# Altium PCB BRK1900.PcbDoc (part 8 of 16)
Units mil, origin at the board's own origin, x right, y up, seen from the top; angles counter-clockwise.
Board outline 8858.27 x 5905.51 mil, 10 copper layers (L1-TOP, L2-GND, L3-PWR, L4-GND, L5-PWR, L6-PWR, L7-GND, L8-SIG, L9-GND, L10-BOT), stack 48.824 mil thick; 456 components, 571 nets, 2296 pads, 2416 vias.
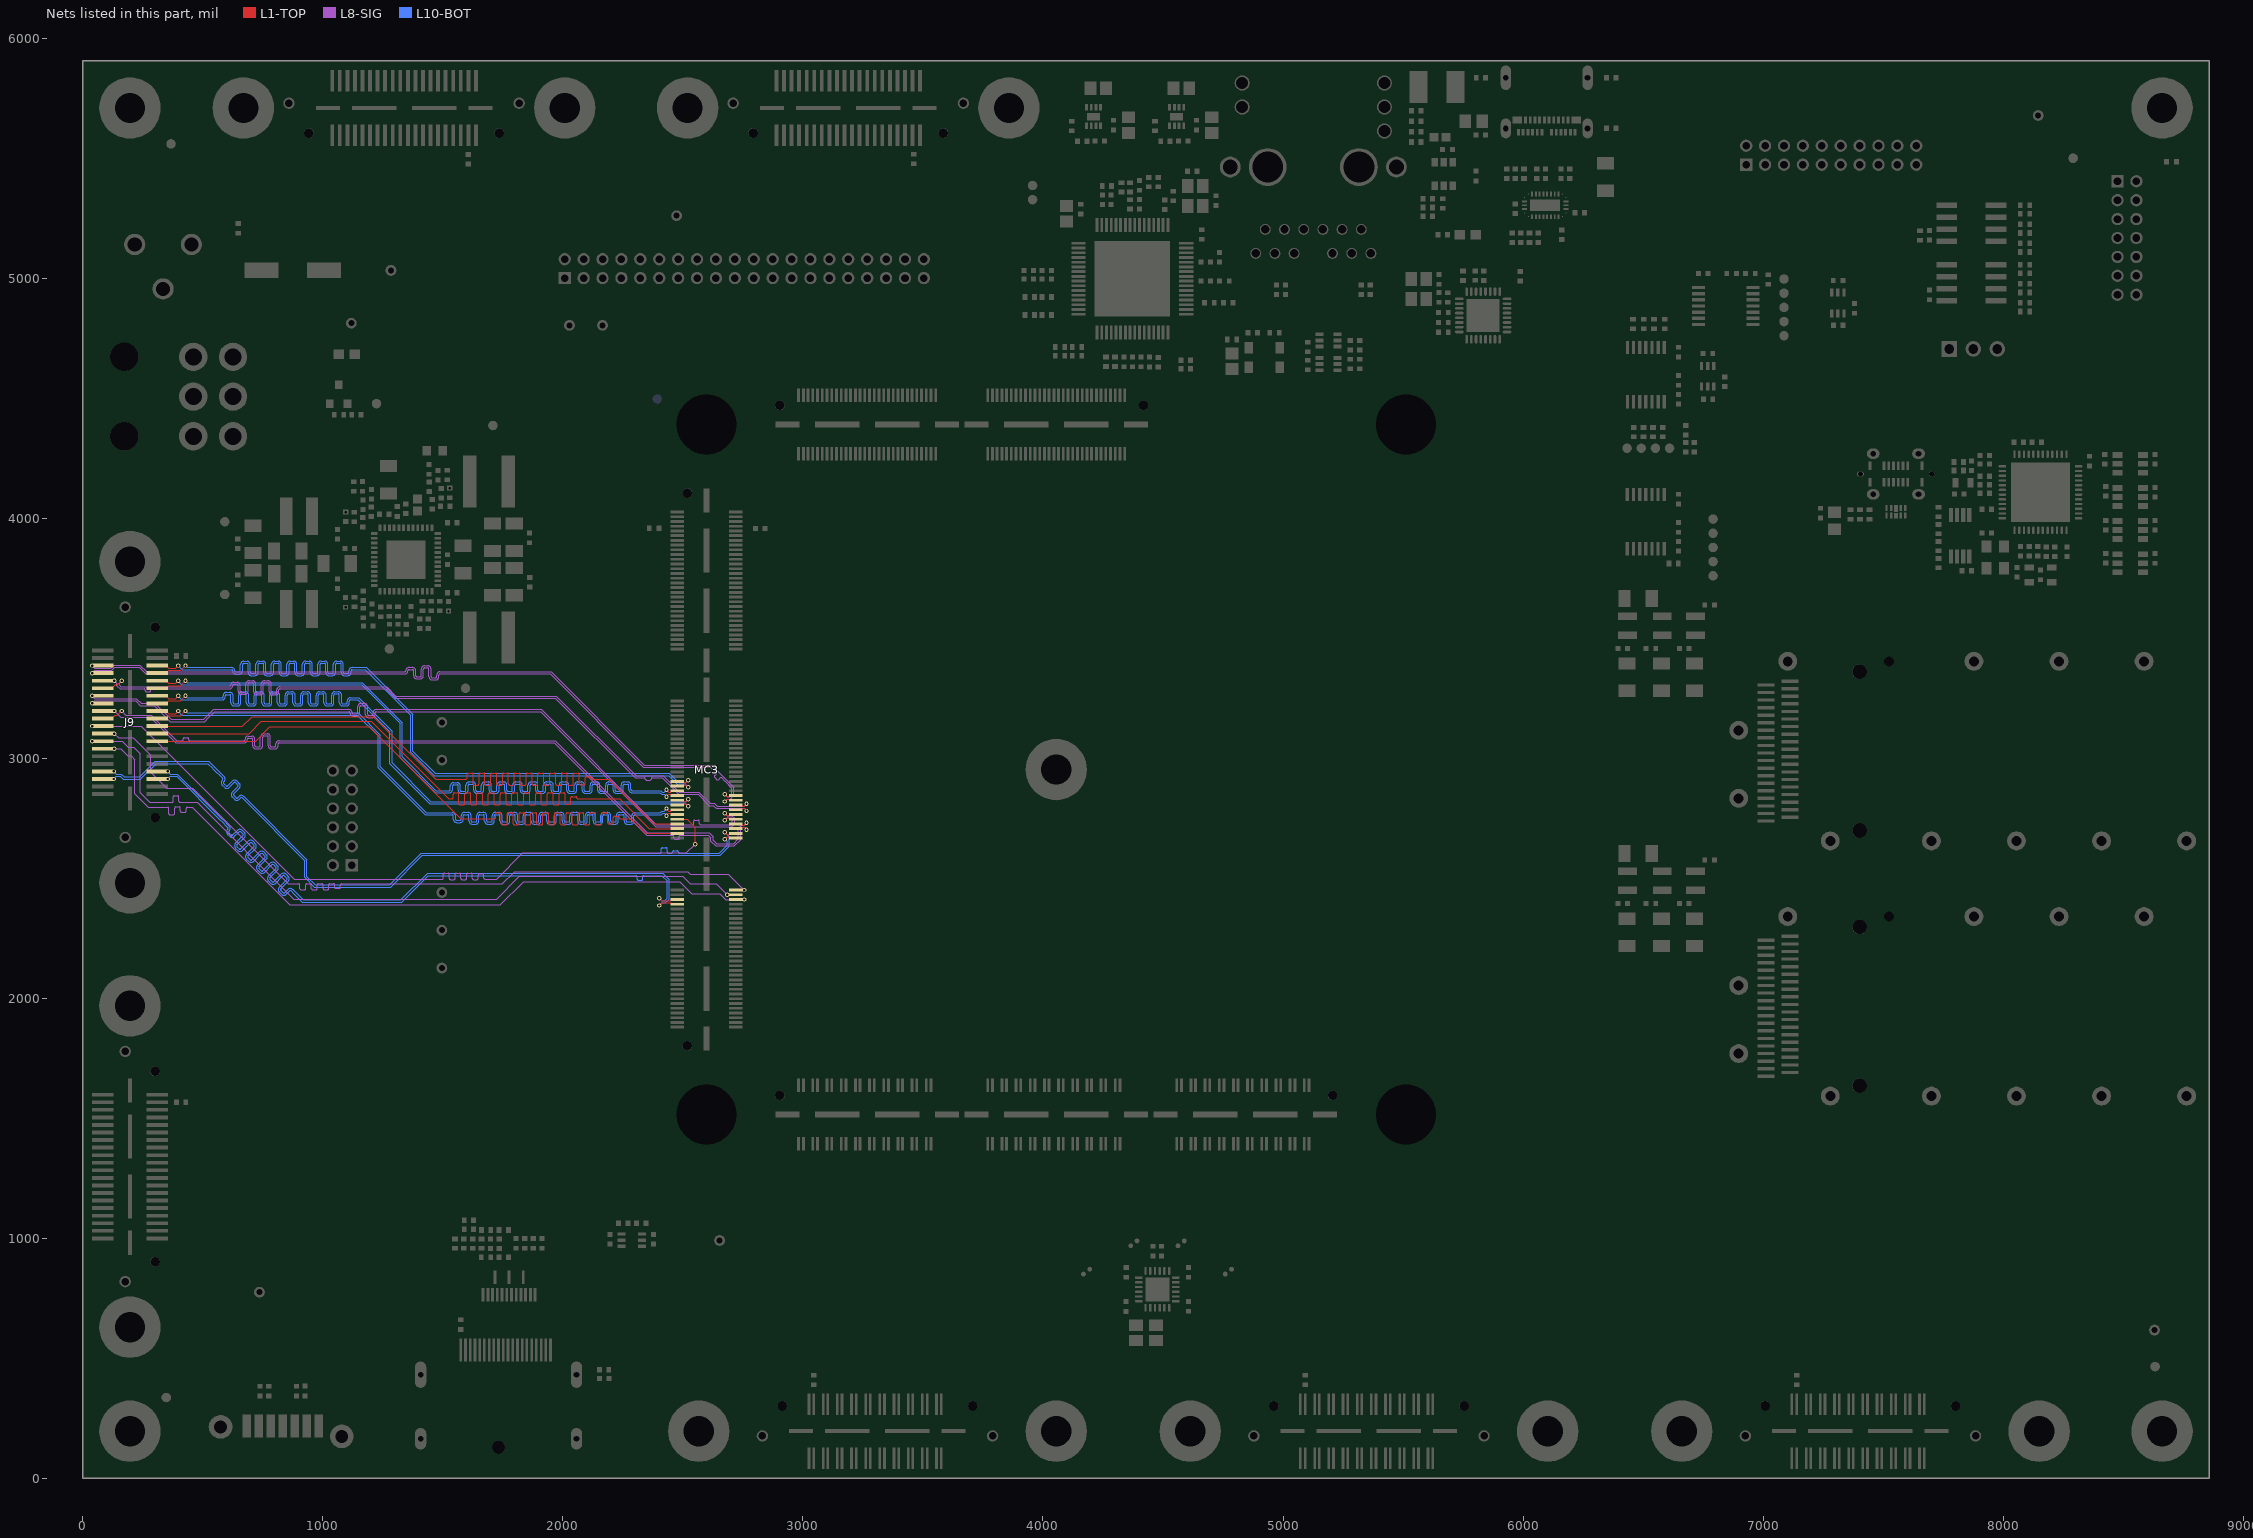
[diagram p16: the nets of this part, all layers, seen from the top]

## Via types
v1: diameter 18, hole 10, L1-TOP to L10-BOT, tented both sides, 2170 vias
v2: diameter 20, hole 10, L1-TOP to L10-BOT, tented both sides, 246 vias

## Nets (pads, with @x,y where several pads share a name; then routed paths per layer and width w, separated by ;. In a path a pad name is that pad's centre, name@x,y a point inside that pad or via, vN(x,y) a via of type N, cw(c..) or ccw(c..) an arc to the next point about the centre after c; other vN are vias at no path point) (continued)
SZG_PORTB_C2P_CLKN: J9.36 MC3.55 | length 3157.5
  L1-TOP w3.3: v1(2401.77,2416.35) 2412.05,2406.08 2448.53,2406.08 2453.88,2411.42 MC3.55@2476.77,2411.42
  L10-BOT w3.3: v1@354.36,2914.39 364.62,2924.66 391,2924.66 573.86,2741.79 576.89,2738.76 604.34,2711.31 cw(c601.08,2707.99) 604.37,2704.69 602.84,2703.16 ccw(c612.5,2693.5) 602.87,2683.82 ; 602.87,2683.81 612.7,2673.99 ccw(c622.38,2683.62) 632.04,2673.96 651.25,2693.17 cw(c654.55,2689.87) 657.84,2693.17 667.73,2683.28 cw(c664.43,2679.99) 667.73,2676.69 ; 667.71,2676.67 636.19,2645.16 ccw(c645.85,2635.5) 636.22,2625.81 646.05,2615.98 ccw(c655.74,2625.61) 663.87,2614.64 664.08,2614.64 696.93,2647.49 cw(c700.23,2644.19) 703.52,2647.49 713.41,2637.6 cw(c710.11,2634.31) 713.41,2631.01 681.87,2599.48 ccw(c691.53,2589.82) 681.9,2580.13 691.73,2570.3 ccw(c701.42,2579.93) 709.55,2568.96 709.76,2568.96 742.61,2601.81 cw(c745.91,2598.52) 749.2,2601.81 759.09,2591.92 cw(c755.79,2588.63) 759.09,2585.33 ; 759.06,2585.31 727.55,2553.8 ccw(c737.21,2544.14) 727.58,2534.45 737.41,2524.62 ccw(c747.1,2534.25) 755.23,2523.28 755.44,2523.28 788.29,2556.13 cw(c791.59,2552.84) 794.88,2556.13 804.77,2546.25 cw(c801.47,2542.95) 804.77,2539.66 773.23,2508.12 ccw(c782.89,2498.46) 773.26,2488.78 783.09,2478.95 ccw(c792.77,2488.58) 800.9,2477.6 801.12,2477.6 833.97,2510.45 cw(c837.26,2507.16) 840.56,2510.45 850.44,2500.57 cw(c847.15,2497.27) 850.44,2493.98 ; 850.42,2493.95 818.91,2462.44 ccw(c828.57,2452.78) 818.94,2443.1 828.77,2433.27 ccw(c838.45,2442.9) 846.58,2431.92 846.79,2431.92 861.97,2447.1 cw(c865.27,2443.8) 868.58,2447.08 ; 868.59,2447.07 869.88,2445.78 872.91,2442.75 915.21,2400.45 1329.58,2400.45 1440.13,2511 2279.53,2511 2304.48,2511 cw(c2304.48,2506.34) 2309.14,2506.34 2309.14,2496.71 ccw(c2313.8,2496.71) 2313.8,2492.05 2327.78,2492.05 ccw(c2327.78,2496.71) 2332.44,2496.71 2332.44,2506.34 cw(c2337.1,2506.34) 2337.1,2511 2381.87,2511 2413,2511 2434.03,2489.97 2434.03,2416.26 2423.85,2406.08 2412.05,2406.08 v1(2401.77,2416.35)
  other v1: 354.36,2913.41
SZG_PORTB_C2P_CLKP: J9.34 MC3.53 | length 3157.6
  L1-TOP w3.3: v1(2401.77,2386.7) 2412.15,2397.08 2448.91,2397.08 2450.46,2395.52 2472.98,2395.52 MC3.53@2476.77,2391.73
  L10-BOT w3.3: v1@354.36,2943.92 364.62,2933.66 394.73,2933.66 580.23,2748.16 583.26,2745.13 610.74,2717.65 612.05,2716.33 612.05,2716.12 cw(c601.08,2707.99) 610.74,2698.33 609.2,2696.8 ccw(c612.5,2693.5) 609.2,2690.21 619.09,2680.32 ccw(c622.38,2683.62) 625.68,2680.32 644.87,2699.51 cw(c654.55,2689.87) 664.21,2699.53 674.09,2689.65 cw(c664.43,2679.99) 675.41,2671.86 675.41,2671.65 642.56,2638.79 ccw(c645.85,2635.5) 642.56,2632.2 652.44,2622.32 ccw(c655.74,2625.61) 659.03,2622.32 690.6,2653.89 cw(c700.23,2644.19) 709.89,2653.85 719.77,2643.97 cw(c710.11,2634.31) 721.09,2626.18 721.09,2625.97 688.24,2593.11 ccw(c691.53,2589.82) 688.24,2586.52 698.12,2576.64 ccw(c701.42,2579.93) 704.71,2576.64 ; 704.73,2576.66 736.28,2608.21 cw(c745.91,2598.52) 755.57,2608.17 765.45,2598.29 cw(c755.79,2588.63) 766.77,2580.5 766.77,2580.29 733.91,2547.43 ccw(c737.21,2544.14) 733.91,2540.84 743.8,2530.96 ccw(c747.1,2534.25) 750.39,2530.96 ; 750.41,2530.98 781.96,2562.53 cw(c791.59,2552.84) 801.24,2562.5 811.13,2552.61 cw(c801.47,2542.95) 812.45,2534.82 812.45,2534.61 779.59,2501.76 ccw(c782.89,2498.46) 779.59,2495.17 789.48,2485.28 ccw(c792.77,2488.58) 796.07,2485.28 ; 796.09,2485.3 827.64,2516.85 cw(c837.26,2507.16) 846.92,2516.82 856.81,2506.93 cw(c847.15,2497.27) 858.13,2489.14 858.13,2488.93 825.27,2456.08 ccw(c828.57,2452.78) 825.27,2449.49 835.16,2439.6 ccw(c838.45,2442.9) 841.75,2439.6 ; 841.77,2439.62 855.61,2453.46 cw(c865.27,2443.8) 873.4,2454.78 873.61,2454.78 874.91,2453.47 ; 874.92,2453.46 876.24,2452.14 879.27,2449.11 918.94,2409.45 1325.85,2409.45 1436.41,2520 2416.73,2520 2443.03,2493.7 2443.03,2412.53 2427.58,2397.08 2412.15,2397.08 v1(2401.77,2386.7)
  other v1: 354.36,2944.91
SZG_PORTB_P2C_CLKN: J9.35 MC3.64 | length 3156.2
  L1-TOP w3.3: v1@2675.08,2690.95 2676.08,2690.95 2685.36,2681.67 2692.1,2681.67 2697.44,2687.01 MC3.64@2720.08,2687.01
  L10-BOT w3.3: v1@128.76,2914.39 139.02,2924.66 157,2924.66 168.66,2913 240.73,2913 305.73,2978 521.08,2978 538.91,2960.17 541.94,2957.14 582.98,2916.1 cw(c579.72,2912.78) 583.01,2909.48 580.83,2907.3 ccw(c590.49,2897.64) 580.86,2887.96 590.69,2878.13 ccw(c600.38,2887.76) 610.04,2878.1 629.89,2897.96 cw(c633.19,2894.66) 636.48,2897.96 646.37,2888.07 cw(c643.07,2884.78) 646.37,2881.48 ; 646.35,2881.46 622.73,2857.84 ccw(c632.39,2848.18) 622.75,2838.5 632.59,2828.67 ccw(c642.27,2838.3) 650.4,2827.32 650.61,2827.32 657.89,2834.6 cw(c661.19,2831.3) 664.5,2834.58 665.8,2833.28 668.83,2830.25 925.2,2573.89 925.2,2503.29 965.04,2463.44 1282.34,2463.44 1414.9,2596 2655.73,2596 2693,2633.27 2693,2673.02 v1@2675.08,2690.95
  other v1: 2675.08,2691.95 128.76,2913.41
SZG_PORTB_P2C_CLKP: J9.33 MC3.62 | length 3157.2
  L1-TOP w3.3: v1@2675.08,2663.39 2676.18,2663.39 2685.46,2672.67 2692.1,2672.67 2697.44,2667.32 MC3.62@2720.08,2667.32
  L10-BOT w3.3: v1@128.76,2943.92 139.02,2933.66 160.73,2933.66 172.38,2922 237,2922 288,2973 302,2987 524.81,2987 545.28,2966.54 548.31,2963.5 589.38,2922.44 ; 589.39,2922.42 590.69,2921.12 590.69,2920.91 cw(c579.72,2912.78) 589.38,2903.12 587.2,2900.94 ccw(c590.49,2897.64) 587.2,2894.35 597.08,2884.46 ccw(c600.38,2887.76) 603.67,2884.46 623.51,2904.3 cw(c633.19,2894.66) 642.85,2904.32 652.73,2894.43 cw(c643.07,2884.78) 654.05,2876.65 654.05,2876.43 629.09,2851.48 ccw(c632.39,2848.18) 629.09,2844.89 638.98,2835 ccw(c642.27,2838.3) 645.57,2835 ; 645.59,2835.02 651.53,2840.96 cw(c661.19,2831.3) 669.32,2842.28 669.53,2842.28 670.84,2840.98 ; 670.85,2840.96 672.17,2839.64 675.2,2836.61 934.2,2577.61 934.2,2507.01 968.77,2472.44 1278.61,2472.44 1411.17,2605 2404.61,2605 2406.26,2605 ccw(c2406.26,2609.66) 2410.92,2609.66 2410.92,2622.6 cw(c2415.58,2622.6) 2415.58,2627.26 2429.56,2627.26 cw(c2429.56,2622.6) 2434.22,2622.6 2434.22,2609.66 ccw(c2438.88,2609.66) 2438.88,2605 2452.86,2605 ccw(c2452.86,2609.66) 2457.52,2609.66 cw(c2462.18,2609.66) 2462.18,2614.32 2476.16,2614.32 cw(c2476.16,2609.66) 2480.82,2609.66 ccw(c2485.48,2609.66) 2485.48,2605 2507.87,2605 2652,2605 2684,2637 2684,2654.46 v1@2675.08,2663.39
  other v1: 2675.08,2662.29 128.76,2944.91
SZG_PORTB_S0_D0P: J9.5 MC3.78 | length 3166.2
  L1-TOP w3.3: v1@2675.08,2820.87 2676.18,2820.87 2685.46,2830.15 2692.1,2830.15 2697.44,2824.8 MC3.78@2720.08,2824.8
  L8-SIG w3.15: v1(39.35,3385.92) 50.61,3374.66 116.66,3374.66 130.21,3388.21 238.52,3388.21 266.65,3360.08 1291.47,3360.08 1341.3,3360.08 ccw(c1341.3,3364.71) 1345.93,3364.71 cw(c1359.56,3364.71) 1359.56,3378.34 1373.45,3378.34 cw(c1373.45,3364.71) 1387.08,3364.71 1387.08,3344.29 ccw(c1391.71,3344.29) 1391.71,3339.66 1405.6,3339.66 ccw(c1405.6,3344.29) 1410.23,3344.29 1410.23,3371.45 cw(c1423.86,3371.45) 1423.86,3385.08 1437.75,3385.08 cw(c1437.75,3371.45) 1451.38,3371.45 1451.38,3339.71 ccw(c1456.01,3339.71) 1456.01,3335.08 1469.9,3335.08 ccw(c1469.9,3339.71) 1474.53,3339.71 1474.53,3346.45 cw(c1488.16,3346.45) 1488.16,3360.08 1494.23,3360.08 1950.95,3360.08 2339.53,2971.5 2619.67,2971.5 2623.65,2967.51 2624.9,2967.51 2712.93,2879.48 2712.93,2845.67 2697.35,2830.1 2685.41,2830.1 v1(2675.08,2819.77)
SZG_PORTB_S1_D1P: J9.6 MC3.83 | length 3202.3
  L1-TOP w3.3: J9.6@309.65,3385.91 346.64,3385.91 357.89,3374.66 386.98,3374.66 v1(398.23,3385.91) ; MC3.83@2476.77,2883.86 2499.41,2883.86 2504.7,2889.15 2512.7,2889.15 2521.77,2880.08 v1@2521.77,2879.92
  L10-BOT w3.3: v1(398.23,3385.91) 398.23,3384.4 413.64,3369 566.73,3369 619.85,3369 cw(c619.85,3364.34) 624.51,3364.34 ccw(c638.17,3364.34) 638.17,3350.68 652.15,3350.68 ccw(c652.15,3364.34) 665.81,3364.34 665.81,3389.91 cw(c670.47,3389.91) 670.47,3394.57 684.45,3394.57 cw(c684.45,3389.91) 689.11,3389.91 689.11,3357.66 ccw(c702.77,3357.66) 702.77,3344 716.75,3344 ccw(c716.75,3357.66) 730.41,3357.66 730.41,3390.75 cw(c735.07,3390.75) 735.07,3395.41 749.05,3395.41 cw(c749.05,3390.75) 753.71,3390.75 753.71,3357.66 ccw(c767.37,3357.66) 767.37,3344 781.35,3344 ccw(c781.35,3357.66) 795.01,3357.66 795.01,3390.75 cw(c799.67,3390.75) 799.67,3395.41 813.65,3395.41 cw(c813.65,3390.75) 818.31,3390.75 818.31,3357.66 ccw(c831.97,3357.66) 831.97,3344 845.95,3344 ccw(c845.95,3357.66) 859.61,3357.66 859.61,3390.75 cw(c864.27,3390.75) 864.27,3395.41 878.25,3395.41 cw(c878.25,3390.75) 882.91,3390.75 882.91,3357.66 ccw(c896.57,3357.66) 896.57,3344 910.55,3344 ccw(c910.55,3357.66) 924.21,3357.66 924.21,3390.75 cw(c928.87,3390.75) 928.87,3395.41 942.85,3395.41 cw(c942.85,3390.75) 947.51,3390.75 947.51,3357.66 ccw(c961.17,3357.66) 961.17,3344 975.15,3344 ccw(c975.15,3357.66) 988.81,3357.66 988.81,3390.75 cw(c993.47,3390.75) 993.47,3395.41 1007.45,3395.41 cw(c1007.45,3390.75) 1012.11,3390.75 1012.11,3357.66 ccw(c1025.77,3357.66) 1025.77,3344 1039.75,3344 ccw(c1039.75,3357.66) 1053.41,3357.66 1053.41,3390.75 cw(c1058.07,3390.75) 1058.07,3395.41 1072.05,3395.41 cw(c1072.05,3390.75) 1076.71,3390.75 1076.71,3357.66 ccw(c1090.37,3357.66) 1090.37,3344 1104.35,3344 ccw(c1104.35,3357.66) 1118.01,3357.66 1118.01,3364.34 cw(c1122.67,3364.34) 1122.67,3369 1128.82,3369 1177.33,3369 1366.53,3179.8 1366.53,3025.47 1463.99,2928.01 2440.37,2928.01 2479.18,2889.2 2512.49,2889.2 v1@2521.77,2879.92
  other v1: 2521.77,2878.82
SZG_PORTB_S2_D0N: J9.7 MC3.80 | length 3166.8
  L1-TOP w3.3: v1@2675.08,2848.43 2676.08,2848.43 2685.36,2839.15 2692.1,2839.15 2697.44,2844.49 MC3.80@2720.08,2844.49
  L8-SIG w3.15: v1(39.35,3354.39) 50.61,3365.66 120.38,3365.66 133.93,3379.21 234.79,3379.21 260.29,3353.71 262.93,3351.08 1291.47,3351.08 1341.3,3351.08 ccw(c1341.3,3364.71) 1354.93,3364.71 cw(c1359.56,3364.71) 1359.56,3369.34 1373.45,3369.34 cw(c1373.45,3364.71) 1378.08,3364.71 1378.08,3344.29 ccw(c1391.71,3344.29) 1391.71,3330.66 1405.6,3330.66 ccw(c1405.6,3344.29) 1419.23,3344.29 1419.23,3371.45 cw(c1423.86,3371.45) 1423.86,3376.08 1437.75,3376.08 cw(c1437.75,3371.45) 1442.38,3371.45 1442.38,3339.71 ccw(c1456.01,3339.71) 1456.01,3326.08 1469.9,3326.08 ccw(c1469.9,3339.71) 1483.53,3339.71 1483.53,3346.45 cw(c1488.16,3346.45) 1488.16,3351.08 1494.23,3351.08 1947.22,3351.08 2335.8,2962.5 2615.94,2962.5 2620.55,2957.88 2620.55,2957 2622.69,2957 2622.73,2956.95 2639.1,2940.58 cw(c2635.83,2937.31) 2639.1,2934.04 2632.28,2927.21 ccw(c2635.55,2923.94) 2632.28,2920.67 2642.1,2910.84 ccw(c2645.38,2914.12) 2648.65,2910.84 2655.47,2917.67 cw(c2658.74,2914.39) 2662.02,2917.67 2672.59,2907.1 2673.7,2905.98 2703.93,2875.76 2703.93,2849.4 2693.62,2839.1 2685.41,2839.1 v1(2675.08,2849.43)
SZG_PORTB_S3_D1N: J9.8 MC3.85 | length 3201.6
  L1-TOP w3.3: J9.8@309.65,3354.41 346.51,3354.41 357.76,3365.66 407.51,3365.66 v1@427.76,3385.9 ; MC3.85@2476.77,2903.54 2499.41,2903.54 2504.8,2898.15 2512.7,2898.15 2521.77,2907.22 v1@2521.77,2907.48
  L10-BOT w3.3: v1@427.76,3385.9 435.66,3378 566.73,3378 619.85,3378 cw(c619.85,3364.34) 633.51,3364.34 ccw(c638.17,3364.34) 638.17,3359.68 652.15,3359.68 ccw(c652.15,3364.34) 656.81,3364.34 656.81,3389.91 cw(c670.47,3389.91) 670.47,3403.57 684.45,3403.57 cw(c684.45,3389.91) 698.11,3389.91 698.11,3357.66 ccw(c702.77,3357.66) 702.77,3353 716.75,3353 ccw(c716.75,3357.66) 721.41,3357.66 721.41,3390.75 cw(c735.07,3390.75) 735.07,3404.41 749.05,3404.41 cw(c749.05,3390.75) 762.71,3390.75 762.71,3357.66 ccw(c767.37,3357.66) 767.37,3353 781.35,3353 ccw(c781.35,3357.66) 786.01,3357.66 786.01,3390.75 cw(c799.67,3390.75) 799.67,3404.41 813.65,3404.41 cw(c813.65,3390.75) 827.31,3390.75 827.31,3357.66 ccw(c831.97,3357.66) 831.97,3353 845.95,3353 ccw(c845.95,3357.66) 850.61,3357.66 850.61,3390.75 cw(c864.27,3390.75) 864.27,3404.41 878.25,3404.41 cw(c878.25,3390.75) 891.91,3390.75 891.91,3357.66 ccw(c896.57,3357.66) 896.57,3353 910.55,3353 ccw(c910.55,3357.66) 915.21,3357.66 915.21,3390.75 cw(c928.87,3390.75) 928.87,3404.41 942.85,3404.41 cw(c942.85,3390.75) 956.51,3390.75 956.51,3357.66 ccw(c961.17,3357.66) 961.17,3353 975.15,3353 ccw(c975.15,3357.66) 979.81,3357.66 979.81,3390.75 cw(c993.47,3390.75) 993.47,3404.41 1007.45,3404.41 cw(c1007.45,3390.75) 1021.11,3390.75 1021.11,3357.66 ccw(c1025.77,3357.66) 1025.77,3353 1039.75,3353 ccw(c1039.75,3357.66) 1044.41,3357.66 1044.41,3390.75 cw(c1058.07,3390.75) 1058.07,3404.41 1072.05,3404.41 cw(c1072.05,3390.75) 1085.71,3390.75 1085.71,3357.66 ccw(c1090.37,3357.66) 1090.37,3353 1104.35,3353 ccw(c1104.35,3357.66) 1109.01,3357.66 1109.01,3364.34 cw(c1122.67,3364.34) 1122.67,3378 1128.82,3378 1181.06,3378 1375.53,3183.53 1375.53,3029.2 1467.72,2937.01 2444.1,2937.01 2482.91,2898.2 2512.49,2898.2 v1@2521.77,2907.48
  other v1: 2521.77,2908.48 428.26,3385.9
SZG_PORTB_S4_D2P: J9.9 MC3.74 | length 3167.8
  L1-TOP w3.3: MC3.74@2720.08,2785.43 2742.72,2785.43 2748.01,2790.73 2756.01,2790.73 2765.08,2781.66 v1@2765.08,2781.5
  L8-SIG w3.15: v1(132.13,3322.91) 142.4,3312.64 142.4,3302.27 155.81,3288.86 230.66,3288.86 255.38,3288.86 cw(c255.38,3284.23) 260.01,3284.23 260.01,3281.82 ccw(c264.64,3281.82) 264.64,3277.19 278.53,3277.19 ccw(c278.53,3281.82) 283.16,3281.82 283.16,3284.23 cw(c287.79,3284.23) 287.79,3288.86 314.96,3288.86 530.33,3288.86 610.86,3288.86 ccw(c610.86,3302.49) 624.49,3302.49 cw(c629.12,3302.49) 629.12,3307.12 643.01,3307.12 cw(c643.01,3302.49) 647.64,3302.49 647.64,3279.6 ccw(c661.27,3279.6) 661.27,3265.97 675.16,3265.97 ccw(c675.16,3279.6) 688.79,3279.6 688.79,3309.23 cw(c693.42,3309.23) 693.42,3313.86 707.31,3313.86 cw(c707.31,3309.23) 711.94,3309.23 711.94,3277.49 ccw(c725.57,3277.49) 725.57,3263.86 739.46,3263.86 ccw(c739.46,3277.49) 753.09,3277.49 753.09,3309.23 cw(c757.72,3309.23) 757.72,3313.86 771.61,3313.86 cw(c771.61,3309.23) 776.24,3309.23 776.24,3277.49 ccw(c789.87,3277.49) 789.87,3263.86 803.76,3263.86 ccw(c803.76,3277.49) 817.39,3277.49 817.39,3284.23 cw(c822.02,3284.23) 822.02,3288.86 828.1,3288.86 1262.14,3288.86 1301,3250 1969.32,3250 2301.57,2917.75 2314.96,2917.75 2339.69,2917.75 cw(c2339.69,2913.12) 2344.32,2913.12 ccw(c2348.95,2913.12) 2348.95,2908.49 2362.84,2908.49 ccw(c2362.84,2913.12) 2367.47,2913.12 cw(c2372.1,2913.12) 2372.1,2917.75 2387.51,2917.75 2414.4,2917.75 2482.16,2850 2563.38,2850 2610.38,2803 2627,2803 2639.22,2790.78 2755.79,2790.78 v1@2765.08,2781.5
  other v1: 2765.08,2780.4
SZG_PORTB_S5_D3P: J9.10 MC3.79 | length 3203
  L1-TOP w3.3: J9.10@309.65,3322.91 346.64,3322.91 357.89,3311.66 386.98,3311.66 v1(398.23,3322.91) ; v1@2431.77,2840.55 2432.87,2840.55 2442.15,2849.83 2448.79,2849.83 2454.13,2844.49 MC3.79@2476.77,2844.49
  L10-BOT w3.3: v1(398.23,3322.91) 398.23,3319.77 412,3306 1161.59,3306 1322.53,3145.06 1322.53,3001.47 1467.73,2856.27 1504.05,2856.27 1527.1,2856.27 ccw(c1527.1,2869.93) 1540.76,2869.93 1540.76,2884.96 cw(c1545.42,2884.96) 1545.42,2889.62 1559.4,2889.62 cw(c1559.4,2884.96) 1564.06,2884.96 1564.06,2866.96 ccw(c1577.72,2866.96) 1577.72,2853.3 1591.7,2853.3 ccw(c1591.7,2866.96) 1605.36,2866.96 1605.36,2887.58 cw(c1610.02,2887.58) 1610.02,2892.24 1624,2892.24 cw(c1624,2887.58) 1628.66,2887.58 1628.66,2866.96 ccw(c1642.32,2866.96) 1642.32,2853.3 1656.3,2853.3 ccw(c1656.3,2866.96) 1669.96,2866.96 1669.96,2887.58 cw(c1674.62,2887.58) 1674.62,2892.24 1688.6,2892.24 cw(c1688.6,2887.58) 1693.26,2887.58 1693.26,2866.96 ccw(c1706.92,2866.96) 1706.92,2853.3 1720.9,2853.3 ccw(c1720.9,2866.96) 1734.56,2866.96 1734.56,2887.58 cw(c1739.22,2887.58) 1739.22,2892.24 1753.2,2892.24 cw(c1753.2,2887.58) 1757.86,2887.58 1757.86,2866.96 ccw(c1771.52,2866.96) 1771.52,2853.3 1785.5,2853.3 ccw(c1785.5,2866.96) 1799.16,2866.96 1799.16,2887.58 cw(c1803.82,2887.58) 1803.82,2892.24 1817.8,2892.24 cw(c1817.8,2887.58) 1822.46,2887.58 1822.46,2866.96 ccw(c1836.12,2866.96) 1836.12,2853.3 1850.1,2853.3 ccw(c1850.1,2866.96) 1863.76,2866.96 1863.76,2887.58 cw(c1868.42,2887.58) 1868.42,2892.24 1882.4,2892.24 cw(c1882.4,2887.58) 1887.06,2887.58 1887.06,2866.96 ccw(c1900.72,2866.96) 1900.72,2853.3 1914.7,2853.3 ccw(c1914.7,2866.96) 1928.36,2866.96 1928.36,2887.58 cw(c1933.02,2887.58) 1933.02,2892.24 1947,2892.24 cw(c1947,2887.58) 1951.66,2887.58 1951.66,2866.96 ccw(c1965.32,2866.96) 1965.32,2853.3 1979.3,2853.3 ccw(c1979.3,2866.96) 1992.96,2866.96 1992.96,2887.58 cw(c1997.62,2887.58) 1997.62,2892.24 2011.6,2892.24 cw(c2011.6,2887.58) 2016.26,2887.58 2016.26,2866.96 ccw(c2029.92,2866.96) 2029.92,2853.3 2043.9,2853.3 ccw(c2043.9,2866.96) 2057.56,2866.96 2057.56,2887.58 cw(c2062.22,2887.58) 2062.22,2892.24 2076.2,2892.24 cw(c2076.2,2887.58) 2080.86,2887.58 2080.86,2866.96 ccw(c2094.52,2866.96) 2094.52,2853.3 2108.5,2853.3 ccw(c2108.5,2866.96) 2122.16,2866.96 2122.16,2887.58 cw(c2126.82,2887.58) 2126.82,2892.24 2140.8,2892.24 cw(c2140.8,2887.58) 2145.46,2887.58 2145.46,2866.96 ccw(c2159.12,2866.96) 2159.12,2853.3 2173.1,2853.3 ccw(c2173.1,2866.96) 2186.76,2866.96 2186.76,2887.58 cw(c2191.42,2887.58) 2191.42,2892.24 2205.4,2892.24 cw(c2205.4,2887.58) 2210.06,2887.58 2210.06,2866.96 ccw(c2223.72,2866.96) 2223.72,2853.3 2237.7,2853.3 ccw(c2237.7,2866.96) 2251.36,2866.96 2251.36,2887.58 cw(c2256.02,2887.58) 2256.02,2892.24 2270,2892.24 cw(c2270,2887.58) 2274.66,2887.58 2274.66,2869.93 ccw(c2288.32,2869.93) 2288.32,2856.27 2326.77,2856.27 2404.6,2856.27 2411.04,2849.83 2422.49,2849.83 v1@2431.77,2840.55
  other v1: 2431.77,2839.45
SZG_PORTB_S6_D2N: J9.11 MC3.76 | length 3217.7
  L1-TOP w3.3: J9.11@84.05,3291.41 120.41,3291.41 135,3306 144.76,3306 v1@161.66,3322.9 ; MC3.76@2720.08,2805.12 2742.72,2805.12 2748.11,2799.73 2756.01,2799.73 2765.08,2808.8 v1@2765.08,2809.06
  L8-SIG w3.15: v1@161.66,3322.9 151.4,3312.64 151.4,3306 159.53,3297.86 530.33,3297.86 610.86,3297.86 ccw(c610.86,3302.49) 615.49,3302.49 cw(c629.12,3302.49) 629.12,3316.12 643.01,3316.12 cw(c643.01,3302.49) 656.64,3302.49 656.64,3279.6 ccw(c661.27,3279.6) 661.27,3274.97 675.16,3274.97 ccw(c675.16,3279.6) 679.79,3279.6 679.79,3309.23 cw(c693.42,3309.23) 693.42,3322.86 707.31,3322.86 cw(c707.31,3309.23) 720.94,3309.23 720.94,3277.49 ccw(c725.57,3277.49) 725.57,3272.86 739.46,3272.86 ccw(c739.46,3277.49) 744.09,3277.49 744.09,3309.23 cw(c757.72,3309.23) 757.72,3322.86 771.61,3322.86 cw(c771.61,3309.23) 785.24,3309.23 785.24,3277.49 ccw(c789.87,3277.49) 789.87,3272.86 803.76,3272.86 ccw(c803.76,3277.49) 808.39,3277.49 808.39,3284.23 cw(c822.02,3284.23) 822.02,3297.86 828.1,3297.86 1265.86,3297.86 1304.73,3259 1973.05,3259 2305.3,2926.75 2418.13,2926.75 2420.77,2924.12 2485.89,2859 2567.11,2859 2614.11,2812 2630.73,2812 2642.95,2799.78 2755.8,2799.78 v1@2765.08,2809.06
  other v1: 2765.08,2810.06 162.16,3322.9
SZG_PORTB_S7_D3N: J9.12 MC3.81 | length 3201.1
  L1-TOP w3.3: J9.12@309.65,3291.41 346.51,3291.41 357.76,3302.66 407.51,3302.66 v1@427.76,3322.9 ; v1@2431.77,2868.11 2432.77,2868.11 2442.05,2858.83 2448.79,2858.83 2454.13,2864.17 MC3.81@2476.77,2864.17
  L10-BOT w3.3: v1@427.76,3322.9 435.66,3315 1165.32,3315 1331.53,3148.79 1331.53,3005.2 1471.46,2865.27 1504.05,2865.27 1527.1,2865.27 ccw(c1527.1,2869.93) 1531.76,2869.93 1531.76,2884.96 cw(c1545.42,2884.96) 1545.42,2898.62 1559.4,2898.62 cw(c1559.4,2884.96) 1573.06,2884.96 1573.06,2866.96 ccw(c1577.72,2866.96) 1577.72,2862.3 1591.7,2862.3 ccw(c1591.7,2866.96) 1596.36,2866.96 1596.36,2887.58 cw(c1610.02,2887.58) 1610.02,2901.24 1624,2901.24 cw(c1624,2887.58) 1637.66,2887.58 1637.66,2866.96 ccw(c1642.32,2866.96) 1642.32,2862.3 1656.3,2862.3 ccw(c1656.3,2866.96) 1660.96,2866.96 1660.96,2887.58 cw(c1674.62,2887.58) 1674.62,2901.24 1688.6,2901.24 cw(c1688.6,2887.58) 1702.26,2887.58 1702.26,2866.96 ccw(c1706.92,2866.96) 1706.92,2862.3 1720.9,2862.3 ccw(c1720.9,2866.96) 1725.56,2866.96 1725.56,2887.58 cw(c1739.22,2887.58) 1739.22,2901.24 1753.2,2901.24 cw(c1753.2,2887.58) 1766.86,2887.58 1766.86,2866.96 ccw(c1771.52,2866.96) 1771.52,2862.3 1785.5,2862.3 ccw(c1785.5,2866.96) 1790.16,2866.96 1790.16,2887.58 cw(c1803.82,2887.58) 1803.82,2901.24 1817.8,2901.24 cw(c1817.8,2887.58) 1831.46,2887.58 1831.46,2866.96 ccw(c1836.12,2866.96) 1836.12,2862.3 1850.1,2862.3 ccw(c1850.1,2866.96) 1854.76,2866.96 1854.76,2887.58 cw(c1868.42,2887.58) 1868.42,2901.24 1882.4,2901.24 cw(c1882.4,2887.58) 1896.06,2887.58 1896.06,2866.96 ccw(c1900.72,2866.96) 1900.72,2862.3 1914.7,2862.3 ccw(c1914.7,2866.96) 1919.36,2866.96 1919.36,2887.58 cw(c1933.02,2887.58) 1933.02,2901.24 1947,2901.24 cw(c1947,2887.58) 1960.66,2887.58 1960.66,2866.96 ccw(c1965.32,2866.96) 1965.32,2862.3 1979.3,2862.3 ccw(c1979.3,2866.96) 1983.96,2866.96 1983.96,2887.58 cw(c1997.62,2887.58) 1997.62,2901.24 2011.6,2901.24 cw(c2011.6,2887.58) 2025.26,2887.58 2025.26,2866.96 ccw(c2029.92,2866.96) 2029.92,2862.3 2043.9,2862.3 ccw(c2043.9,2866.96) 2048.56,2866.96 2048.56,2887.58 cw(c2062.22,2887.58) 2062.22,2901.24 2076.2,2901.24 cw(c2076.2,2887.58) 2089.86,2887.58 2089.86,2866.96 ccw(c2094.52,2866.96) 2094.52,2862.3 2108.5,2862.3 ccw(c2108.5,2866.96) 2113.16,2866.96 2113.16,2887.58 cw(c2126.82,2887.58) 2126.82,2901.24 2140.8,2901.24 cw(c2140.8,2887.58) 2154.46,2887.58 2154.46,2866.96 ccw(c2159.12,2866.96) 2159.12,2862.3 2173.1,2862.3 ccw(c2173.1,2866.96) 2177.76,2866.96 2177.76,2887.58 cw(c2191.42,2887.58) 2191.42,2901.24 2205.4,2901.24 cw(c2205.4,2887.58) 2219.06,2887.58 2219.06,2866.96 ccw(c2223.72,2866.96) 2223.72,2862.3 2237.7,2862.3 ccw(c2237.7,2866.96) 2242.36,2866.96 2242.36,2887.58 cw(c2256.02,2887.58) 2256.02,2901.24 2270,2901.24 cw(c2270,2887.58) 2283.66,2887.58 2283.66,2869.93 ccw(c2288.32,2869.93) 2288.32,2865.27 2326.77,2865.27 2408.33,2865.27 2414.76,2858.83 2422.49,2858.83 v1@2431.77,2868.11
  other v1: 2431.77,2869.11 428.26,3322.9
SZG_PORTB_S8_D4P: J9.13 MC3.70 | length 3169.6
  L1-TOP w3.3: v1@2675.08,2742.13 2676.18,2742.13 2685.46,2751.41 2692.1,2751.41 2697.44,2746.06 MC3.70@2720.08,2746.06
  L8-SIG w3.15: v1@36.96,3262.31 v1(39.35,3259.92) 50.61,3248.66 223.78,3248.66 244.09,3228.35 301.38,3228.35 304.02,3225.71 368.31,3161.42 503.94,3161.42 521.37,3178.85 545.52,3203 1015.3,3203 1108.61,3203 cw(c1108.61,3189.37) 1122.24,3189.37 1122.24,3189.13 ccw(c1126.87,3189.13) 1126.87,3184.5 1140.76,3184.5 ccw(c1140.76,3189.13) 1145.39,3189.13 1145.39,3214.37 cw(c1159.02,3214.37) 1159.02,3228 1172.91,3228 cw(c1172.91,3214.37) 1186.54,3214.37 1186.54,3182.63 ccw(c1191.17,3182.63) 1191.17,3178 1205.06,3178 ccw(c1205.06,3182.63) 1209.69,3182.63 1209.69,3189.37 cw(c1223.32,3189.37) 1223.32,3203 1229.4,3203 1910.77,3203 2390.07,2723.7 2539.07,2723.7 2540.65,2723.7 ccw(c2540.65,2728.33) 2545.28,2728.33 2545.28,2737.94 cw(c2549.91,2737.94) 2549.91,2742.57 2563.8,2742.57 cw(c2563.8,2737.94) 2568.43,2737.94 2568.43,2728.33 ccw(c2573.06,2728.33) 2573.06,2723.7 2612,2723.7 2700.08,2723.7 2706.27,2729.89 2706.27,2745.78 2700.69,2751.36 2685.41,2751.36 v1(2675.08,2741.03)
SZG_PORTB_S9_D5P: J9.14 MC3.75 | length 3202.3
  L1-TOP w3.3: J9.14@309.65,3259.91 346.64,3259.91 357.89,3248.66 386.98,3248.66 v1(398.23,3259.91) ; MC3.75@2476.77,2805.12 2499.41,2805.12 2504.7,2810.41 2512.7,2810.41 2521.77,2801.34 v1@2521.77,2801.18
  L10-BOT w3.3: v1(398.23,3259.91) 398.23,3257.35 412.59,3243 543.69,3243 580.31,3243 ccw(c580.31,3256.66) 593.97,3256.66 593.97,3260.68 cw(c598.63,3260.68) 598.63,3265.34 612.61,3265.34 cw(c612.61,3260.68) 617.27,3260.68 617.27,3231.66 ccw(c630.93,3231.66) 630.93,3218 644.91,3218 ccw(c644.91,3231.66) 658.57,3231.66 658.57,3263.34 cw(c663.23,3263.34) 663.23,3268 677.21,3268 cw(c677.21,3263.34) 681.87,3263.34 681.87,3231.66 ccw(c695.53,3231.66) 695.53,3218 709.51,3218 ccw(c709.51,3231.66) 723.17,3231.66 723.17,3263.34 cw(c727.83,3263.34) 727.83,3268 741.81,3268 cw(c741.81,3263.34) 746.47,3263.34 746.47,3231.66 ccw(c760.13,3231.66) 760.13,3218 774.11,3218 ccw(c774.11,3231.66) 787.77,3231.66 787.77,3263.34 cw(c792.43,3263.34) 792.43,3268 806.41,3268 cw(c806.41,3263.34) 811.07,3263.34 811.07,3231.66 ccw(c824.73,3231.66) 824.73,3218 838.71,3218 ccw(c838.71,3231.66) 852.37,3231.66 852.37,3263.34 cw(c857.03,3263.34) 857.03,3268 871.01,3268 cw(c871.01,3263.34) 875.67,3263.34 875.67,3231.66 ccw(c889.33,3231.66) 889.33,3218 903.31,3218 ccw(c903.31,3231.66) 916.97,3231.66 916.97,3263.34 cw(c921.63,3263.34) 921.63,3268 935.61,3268 cw(c935.61,3263.34) 940.27,3263.34 940.27,3231.66 ccw(c953.93,3231.66) 953.93,3218 967.91,3218 ccw(c967.91,3231.66) 981.57,3231.66 981.57,3263.34 cw(c986.23,3263.34) 986.23,3268 1000.21,3268 cw(c1000.21,3263.34) 1004.87,3263.34 1004.87,3231.66 ccw(c1018.53,3231.66) 1018.53,3218 1032.51,3218 ccw(c1032.51,3231.66) 1046.17,3231.66 1046.17,3263.34 cw(c1050.83,3263.34) 1050.83,3268 1064.81,3268 cw(c1064.81,3263.34) 1069.47,3263.34 1069.47,3231.66 ccw(c1083.13,3231.66) 1083.13,3218 1097.11,3218 ccw(c1097.11,3231.66) 1110.77,3231.66 1110.77,3238.34 cw(c1115.43,3238.34) 1115.43,3243 1121.58,3243 1145.85,3243 1279.53,3109.32 1279.53,2977.47 1446.54,2810.46 2512.49,2810.46 v1@2521.77,2801.18
  other v1: 2521.77,2800.08
SZG_PORTB_S10_D4N: J9.15 MC3.72 | length 3166.2
  L1-TOP w3.3: v1@2675.08,2769.69 2676.08,2769.69 2685.36,2760.41 2692.1,2760.41 2697.44,2765.75 MC3.72@2720.08,2765.75
  L8-SIG w3.15: v1(39.35,3228.39) 50.61,3239.66 220.06,3239.66 240.37,3219.35 297.65,3219.35 361.95,3155.05 364.58,3152.42 507.66,3152.42 525.1,3169.85 549.25,3194 1015.3,3194 1108.61,3194 cw(c1108.61,3189.37) 1113.24,3189.37 1113.24,3189.13 ccw(c1126.87,3189.13) 1126.87,3175.5 1140.76,3175.5 ccw(c1140.76,3189.13) 1154.39,3189.13 1154.39,3214.37 cw(c1159.02,3214.37) 1159.02,3219 1172.91,3219 cw(c1172.91,3214.37) 1177.54,3214.37 1177.54,3182.63 ccw(c1191.17,3182.63) 1191.17,3169 1205.06,3169 ccw(c1205.06,3182.63) 1218.69,3182.63 1218.69,3189.37 cw(c1223.32,3189.37) 1223.32,3194 1229.4,3194 1907.05,3194 2386.35,2714.7 2703.81,2714.7 2715.27,2726.16 2715.27,2749.51 2704.42,2760.36 2685.41,2760.36 v1(2675.08,2770.69)
SZG_PORTB_S11_D5N: J9.16 MC3.77 | length 3200.9
  L1-TOP w3.3: J9.16@309.65,3228.41 346.51,3228.41 357.76,3239.66 407.51,3239.66 v1@427.76,3259.9 ; MC3.77@2476.77,2824.8 2499.41,2824.8 2504.8,2819.41 2512.7,2819.41 2521.77,2828.48 v1@2521.77,2828.74
  L10-BOT w3.3: v1@427.76,3259.9 435.66,3252 543.69,3252 580.31,3252 ccw(c580.31,3256.66) 584.97,3256.66 584.97,3260.68 cw(c598.63,3260.68) 598.63,3274.34 612.61,3274.34 cw(c612.61,3260.68) 626.27,3260.68 626.27,3231.66 ccw(c630.93,3231.66) 630.93,3227 644.91,3227 ccw(c644.91,3231.66) 649.57,3231.66 649.57,3263.34 cw(c663.23,3263.34) 663.23,3277 677.21,3277 cw(c677.21,3263.34) 690.87,3263.34 690.87,3231.66 ccw(c695.53,3231.66) 695.53,3227 709.51,3227 ccw(c709.51,3231.66) 714.17,3231.66 714.17,3263.34 cw(c727.83,3263.34) 727.83,3277 741.81,3277 cw(c741.81,3263.34) 755.47,3263.34 755.47,3231.66 ccw(c760.13,3231.66) 760.13,3227 774.11,3227 ccw(c774.11,3231.66) 778.77,3231.66 778.77,3263.34 cw(c792.43,3263.34) 792.43,3277 806.41,3277 cw(c806.41,3263.34) 820.07,3263.34 820.07,3231.66 ccw(c824.73,3231.66) 824.73,3227 838.71,3227 ccw(c838.71,3231.66) 843.37,3231.66 843.37,3263.34 cw(c857.03,3263.34) 857.03,3277 871.01,3277 cw(c871.01,3263.34) 884.67,3263.34 884.67,3231.66 ccw(c889.33,3231.66) 889.33,3227 903.31,3227 ccw(c903.31,3231.66) 907.97,3231.66 907.97,3263.34 cw(c921.63,3263.34) 921.63,3277 935.61,3277 cw(c935.61,3263.34) 949.27,3263.34 949.27,3231.66 ccw(c953.93,3231.66) 953.93,3227 967.91,3227 ccw(c967.91,3231.66) 972.57,3231.66 972.57,3263.34 cw(c986.23,3263.34) 986.23,3277 1000.21,3277 cw(c1000.21,3263.34) 1013.87,3263.34 1013.87,3231.66 ccw(c1018.53,3231.66) 1018.53,3227 1032.51,3227 ccw(c1032.51,3231.66) 1037.17,3231.66 1037.17,3263.34 cw(c1050.83,3263.34) 1050.83,3277 1064.81,3277 cw(c1064.81,3263.34) 1078.47,3263.34 1078.47,3231.66 ccw(c1083.13,3231.66) 1083.13,3227 1097.11,3227 ccw(c1097.11,3231.66) 1101.77,3231.66 1101.77,3238.34 cw(c1115.43,3238.34) 1115.43,3252 1121.58,3252 1149.57,3252 1288.53,3113.05 1288.53,2981.2 1450.27,2819.46 2512.49,2819.46 v1@2521.77,2828.74
  other v1: 2521.77,2829.74 428.26,3259.9
SZG_PORTB_S12_D6P: J9.17 MC3.66 | length 3169.5
  L1-TOP w3.3: MC3.66@2720.08,2706.69 2742.72,2706.69 2748.01,2711.99 2756.01,2711.99 2765.08,2702.92 v1@2765.08,2702.76
  L8-SIG w3.15: v1(132.13,3196.91) 159.14,3169.9 282.1,3169.9 385.36,3066.64 388,3064 566.71,3064 671.67,3064 ccw(c671.67,3077.63) 685.3,3077.63 685.3,3078.87 cw(c689.93,3078.87) 689.93,3083.5 703.82,3083.5 cw(c703.82,3078.87) 708.45,3078.87 708.45,3052.63 ccw(c722.08,3052.63) 722.08,3039 735.97,3039 ccw(c735.97,3052.63) 749.6,3052.63 749.6,3088.4 cw(c754.23,3088.4) 754.23,3093.03 768.12,3093.03 cw(c768.12,3088.4) 772.75,3088.4 772.75,3052.63 ccw(c786.38,3052.63) 786.38,3039 800.27,3039 ccw(c800.27,3052.63) 813.9,3052.63 813.9,3059.37 cw(c818.53,3059.37) 818.53,3064 824.6,3064 1964.41,3064 2348.74,2679.68 2433.07,2679.68 2457.8,2679.68 cw(c2457.8,2675.05) 2462.43,2675.05 2462.43,2668.03 ccw(c2467.06,2668.03) 2467.06,2663.4 2480.95,2663.4 ccw(c2480.95,2668.03) 2485.58,2668.03 2485.58,2675.05 cw(c2490.21,2675.05) 2490.21,2679.68 2511.81,2679.68 2606.22,2679.68 2616.67,2669.22 2616.67,2654.71 2636.39,2635 2714.66,2635 2740.16,2660.5 2740.16,2704.11 2748.03,2711.99 2754.75,2711.99 v1(2765.08,2701.66)
SZG_PORTB_S13_D7P: J9.18 MC3.71 | length 3203
  L1-TOP w3.3: J9.18@309.65,3196.91 346.64,3196.91 357.89,3185.66 386.98,3185.66 v1(398.23,3196.91) ; v1@2431.77,2761.81 2432.87,2761.81 2442.15,2771.09 2448.79,2771.09 2454.13,2765.75 MC3.71@2476.77,2765.75
  L10-BOT w3.3: v1(398.23,3196.91) 398.23,3195.27 413.51,3180 586.61,3180 1143.77,3180 1231,3092.77 1231,2960 1427,2764 1507.35,2764 1539.72,2764 cw(c1539.72,2759.34) 1544.38,2759.34 1544.38,2745.76 ccw(c1558.04,2745.76) 1558.04,2732.1 1572.02,2732.1 ccw(c1572.02,2745.76) 1585.68,2745.76 1585.68,2760.8 cw(c1590.34,2760.8) 1590.34,2765.46 1604.32,2765.46 cw(c1604.32,2760.8) 1608.98,2760.8 1608.98,2739.1 ccw(c1622.64,2739.1) 1622.64,2725.44 1636.62,2725.44 ccw(c1636.62,2739.1) 1650.28,2739.1 1650.28,2760.8 cw(c1654.94,2760.8) 1654.94,2765.46 1668.92,2765.46 cw(c1668.92,2760.8) 1673.58,2760.8 1673.58,2739.1 ccw(c1687.24,2739.1) 1687.24,2725.44 1701.22,2725.44 ccw(c1701.22,2739.1) 1714.88,2739.1 1714.88,2760.8 cw(c1719.54,2760.8) 1719.54,2765.46 1733.52,2765.46 cw(c1733.52,2760.8) 1738.18,2760.8 1738.18,2739.1 ccw(c1751.84,2739.1) 1751.84,2725.44 1765.82,2725.44 ccw(c1765.82,2739.1) 1779.48,2739.1 1779.48,2760.8 cw(c1784.14,2760.8) 1784.14,2765.46 1798.12,2765.46 cw(c1798.12,2760.8) 1802.78,2760.8 1802.78,2739.1 ccw(c1816.44,2739.1) 1816.44,2725.44 1830.42,2725.44 ccw(c1830.42,2739.1) 1844.08,2739.1 1844.08,2760.8 cw(c1848.74,2760.8) 1848.74,2765.46 1862.72,2765.46 cw(c1862.72,2760.8) 1867.38,2760.8 1867.38,2739.1 ccw(c1881.04,2739.1) 1881.04,2725.44 1895.02,2725.44 ccw(c1895.02,2739.1) 1908.68,2739.1 1908.68,2760.8 cw(c1913.34,2760.8) 1913.34,2765.46 1927.32,2765.46 cw(c1927.32,2760.8) 1931.98,2760.8 1931.98,2739.1 ccw(c1945.64,2739.1) 1945.64,2725.44 1959.62,2725.44 ccw(c1959.62,2739.1) 1973.28,2739.1 1973.28,2760.8 cw(c1977.94,2760.8) 1977.94,2765.46 1991.92,2765.46 cw(c1991.92,2760.8) 1996.58,2760.8 1996.58,2739.1 ccw(c2010.24,2739.1) 2010.24,2725.44 2024.22,2725.44 ccw(c2024.22,2739.1) 2037.88,2739.1 2037.88,2760.8 cw(c2042.54,2760.8) 2042.54,2765.46 2056.52,2765.46 cw(c2056.52,2760.8) 2061.18,2760.8 2061.18,2739.1 ccw(c2074.84,2739.1) 2074.84,2725.44 2088.82,2725.44 ccw(c2088.82,2739.1) 2102.48,2739.1 2102.48,2760.8 cw(c2107.14,2760.8) 2107.14,2765.46 2121.12,2765.46 cw(c2121.12,2760.8) 2125.78,2760.8 2125.78,2739.1 ccw(c2139.44,2739.1) 2139.44,2725.44 2153.42,2725.44 ccw(c2153.42,2739.1) 2167.08,2739.1 2167.08,2760.8 cw(c2171.74,2760.8) 2171.74,2765.46 2185.72,2765.46 cw(c2185.72,2760.8) 2190.38,2760.8 2190.38,2739.1 ccw(c2204.04,2739.1) 2204.04,2725.44 2218.02,2725.44 ccw(c2218.02,2739.1) 2231.68,2739.1 2231.68,2760.8 cw(c2236.34,2760.8) 2236.34,2765.46 2250.32,2765.46 cw(c2250.32,2760.8) 2254.98,2760.8 2254.98,2739.1 ccw(c2268.64,2739.1) 2268.64,2725.44 2282.62,2725.44 ccw(c2282.62,2739.1) 2296.28,2739.1 2296.28,2759.34 cw(c2300.94,2759.34) 2300.94,2764 2307.09,2764 2408.91,2764 2416,2771.09 2422.49,2771.09 v1@2431.77,2761.81
  other v1: 2431.77,2760.71
SZG_PORTB_S14_D6N: J9.19 MC3.68 | length 3219.8
  L1-TOP w3.3: J9.19@84.05,3165.41 120.41,3165.41 135,3180 144.76,3180 v1@161.66,3196.9 ; MC3.68@2720.08,2726.38 2742.72,2726.38 2748.11,2720.99 2756.01,2720.99 2765.08,2730.06 v1@2765.08,2730.32
  L8-SIG w3.15: v1@161.66,3196.9 179.67,3178.9 285.83,3178.9 391.73,3073 412.58,3073 414.16,3073 ccw(c414.16,3077.63) 418.79,3077.63 418.79,3081.03 cw(c423.42,3081.03) 423.42,3085.66 437.31,3085.66 cw(c437.31,3081.03) 441.94,3081.03 441.94,3077.63 ccw(c446.57,3077.63) 446.57,3073 472.44,3073 566.71,3073 671.67,3073 ccw(c671.67,3077.63) 676.3,3077.63 676.3,3078.87 cw(c689.93,3078.87) 689.93,3092.5 703.82,3092.5 cw(c703.82,3078.87) 717.45,3078.87 717.45,3052.63 ccw(c722.08,3052.63) 722.08,3048 735.97,3048 ccw(c735.97,3052.63) 740.6,3052.63 740.6,3088.4 cw(c754.23,3088.4) 754.23,3102.03 768.12,3102.03 cw(c768.12,3088.4) 781.75,3088.4 781.75,3052.63 ccw(c786.38,3052.63) 786.38,3048 800.27,3048 ccw(c800.27,3052.63) 804.9,3052.63 804.9,3059.37 cw(c818.53,3059.37) 818.53,3073 824.6,3073 1968.14,3073 2352.46,2688.68 2609.95,2688.68 2625.67,2672.95 2625.67,2658.44 2640.12,2644 2710.93,2644 2731.16,2664.23 2731.16,2707.84 2744.3,2720.99 2754.75,2720.99 v1(2765.08,2731.32)
  other v1: 162.16,3196.9
SZG_PORTB_S15_D7N: J9.20 MC3.73 | length 3202
  L1-TOP w3.3: J9.20@309.65,3165.41 346.51,3165.41 357.76,3176.66 407.51,3176.66 v1@427.76,3196.9 ; v1@2431.77,2789.37 2432.77,2789.37 2442.05,2780.09 2448.79,2780.09 2454.13,2785.43 MC3.73@2476.77,2785.43
  L10-BOT w3.3: v1@427.76,3196.9 435.66,3189 1147.5,3189 1240,3096.5 1240,2963.73 1430.73,2773 1507.35,2773 1539.72,2773 cw(c1539.72,2759.34) 1553.38,2759.34 1553.38,2745.76 ccw(c1558.04,2745.76) 1558.04,2741.1 1572.02,2741.1 ccw(c1572.02,2745.76) 1576.68,2745.76 1576.68,2760.8 cw(c1590.34,2760.8) 1590.34,2774.46 1604.32,2774.46 cw(c1604.32,2760.8) 1617.98,2760.8 1617.98,2739.1 ccw(c1622.64,2739.1) 1622.64,2734.44 1636.62,2734.44 ccw(c1636.62,2739.1) 1641.28,2739.1 1641.28,2760.8 cw(c1654.94,2760.8) 1654.94,2774.46 1668.92,2774.46 cw(c1668.92,2760.8) 1682.58,2760.8 1682.58,2739.1 ccw(c1687.24,2739.1) 1687.24,2734.44 1701.22,2734.44 ccw(c1701.22,2739.1) 1705.88,2739.1 1705.88,2760.8 cw(c1719.54,2760.8) 1719.54,2774.46 1733.52,2774.46 cw(c1733.52,2760.8) 1747.18,2760.8 1747.18,2739.1 ccw(c1751.84,2739.1) 1751.84,2734.44 1765.82,2734.44 ccw(c1765.82,2739.1) 1770.48,2739.1 1770.48,2760.8 cw(c1784.14,2760.8) 1784.14,2774.46 1798.12,2774.46 cw(c1798.12,2760.8) 1811.78,2760.8 1811.78,2739.1 ccw(c1816.44,2739.1) 1816.44,2734.44 1830.42,2734.44 ccw(c1830.42,2739.1) 1835.08,2739.1 1835.08,2760.8 cw(c1848.74,2760.8) 1848.74,2774.46 1862.72,2774.46 cw(c1862.72,2760.8) 1876.38,2760.8 1876.38,2739.1 ccw(c1881.04,2739.1) 1881.04,2734.44 1895.02,2734.44 ccw(c1895.02,2739.1) 1899.68,2739.1 1899.68,2760.8 cw(c1913.34,2760.8) 1913.34,2774.46 1927.32,2774.46 cw(c1927.32,2760.8) 1940.98,2760.8 1940.98,2739.1 ccw(c1945.64,2739.1) 1945.64,2734.44 1959.62,2734.44 ccw(c1959.62,2739.1) 1964.28,2739.1 1964.28,2760.8 cw(c1977.94,2760.8) 1977.94,2774.46 1991.92,2774.46 cw(c1991.92,2760.8) 2005.58,2760.8 2005.58,2739.1 ccw(c2010.24,2739.1) 2010.24,2734.44 2024.22,2734.44 ccw(c2024.22,2739.1) 2028.88,2739.1 2028.88,2760.8 cw(c2042.54,2760.8) 2042.54,2774.46 2056.52,2774.46 cw(c2056.52,2760.8) 2070.18,2760.8 2070.18,2739.1 ccw(c2074.84,2739.1) 2074.84,2734.44 2088.82,2734.44 ccw(c2088.82,2739.1) 2093.48,2739.1 2093.48,2760.8 cw(c2107.14,2760.8) 2107.14,2774.46 2121.12,2774.46 cw(c2121.12,2760.8) 2134.78,2760.8 2134.78,2739.1 ccw(c2139.44,2739.1) 2139.44,2734.44 2153.42,2734.44 ccw(c2153.42,2739.1) 2158.08,2739.1 2158.08,2760.8 cw(c2171.74,2760.8) 2171.74,2774.46 2185.72,2774.46 cw(c2185.72,2760.8) 2199.38,2760.8 2199.38,2739.1 ccw(c2204.04,2739.1) 2204.04,2734.44 2218.02,2734.44 ccw(c2218.02,2739.1) 2222.68,2739.1 2222.68,2760.8 cw(c2236.34,2760.8) 2236.34,2774.46 2250.32,2774.46 cw(c2250.32,2760.8) 2263.98,2760.8 2263.98,2739.1 ccw(c2268.64,2739.1) 2268.64,2734.44 2282.62,2734.44 ccw(c2282.62,2739.1) 2287.28,2739.1 2287.28,2759.34 cw(c2300.94,2759.34) 2300.94,2773 2307.09,2773 2405.18,2773 2412.27,2780.09 2422.49,2780.09 v1@2431.77,2789.37
  other v1: 2431.77,2790.37 428.26,3196.9
SZG_PORTB_S16: J9.21 MC3.69 | length 3168.3
  L1-TOP w4.55: MC3.69@2476.77,2746.06 2517.72,2746.06 2551.18,2712.6 v1(2551.18,2641.73)
  L8-SIG w4.05: v1@36.05,3133.91 244.09,3133.91 881.94,2496.06 1496.06,2496.06 1498.09,2496.06 ccw(c1498.09,2500.87) 1502.9,2500.87 1502.9,2516.25 cw(c1507.71,2516.25) 1507.71,2521.06 1522.14,2521.06 cw(c1522.14,2516.25) 1526.95,2516.25 1526.95,2499.51 ccw(c1531.76,2499.51) 1531.76,2494.7 1546.19,2494.7 ccw(c1546.19,2499.51) 1551,2499.51 1551,2516.25 cw(c1555.81,2516.25) 1555.81,2521.06 1570.24,2521.06 cw(c1570.24,2516.25) 1575.05,2516.25 1575.05,2499.51 ccw(c1579.86,2499.51) 1579.86,2494.7 1594.29,2494.7 ccw(c1594.29,2499.51) 1599.1,2499.51 1599.1,2516.25 cw(c1603.91,2516.25) 1603.91,2521.06 1618.34,2521.06 cw(c1618.34,2516.25) 1623.15,2516.25 1623.15,2499.51 ccw(c1627.96,2499.51) 1627.96,2494.7 1642.39,2494.7 ccw(c1642.39,2499.51) 1647.2,2499.51 1647.2,2513.43 cw(c1652.01,2513.43) 1652.01,2518.24 1666.44,2518.24 cw(c1666.44,2513.43) 1671.25,2513.43 1671.25,2500.87 ccw(c1676.06,2500.87) 1676.06,2496.06 1708.66,2496.06 1724.41,2496.06 1833.85,2605.5 2514.95,2605.5 v1(2551.18,2641.73)
  other v1: 39.35,3133.91
SZG_PORTB_S17: J9.22 MC3.67 | length 3294.4
  L1-TOP w4.55: J9.22@309.65,3133.91 665.4,3133.91 705.21,3173.72 1210.54,3173.72 1470.87,2913.39 1594.49,2913.39 1596.76,2913.39 ccw(c1596.76,2918.3) 1601.67,2918.3 1601.67,2933.48 cw(c1606.58,2933.48) 1606.58,2938.39 1621.31,2938.39 cw(c1621.31,2933.48) 1626.22,2933.48 1626.22,2893.3 ccw(c1631.13,2893.3) 1631.13,2888.39 1645.86,2888.39 ccw(c1645.86,2893.3) 1650.77,2893.3 1650.77,2933.48 cw(c1655.68,2933.48) 1655.68,2938.39 1670.41,2938.39 cw(c1670.41,2933.48) 1675.32,2933.48 1675.32,2893.3 ccw(c1680.23,2893.3) 1680.23,2888.39 1694.96,2888.39 ccw(c1694.96,2893.3) 1699.87,2893.3 1699.87,2933.48 cw(c1704.78,2933.48) 1704.78,2938.39 1719.51,2938.39 cw(c1719.51,2933.48) 1724.42,2933.48 1724.42,2893.3 ccw(c1729.33,2893.3) 1729.33,2888.39 1744.06,2888.39 ccw(c1744.06,2893.3) 1748.97,2893.3 1748.97,2933.48 cw(c1753.88,2933.48) 1753.88,2938.39 1768.61,2938.39 cw(c1768.61,2933.48) 1773.52,2933.48 1773.52,2893.3 ccw(c1778.43,2893.3) 1778.43,2888.39 1793.16,2888.39 ccw(c1793.16,2893.3) 1798.07,2893.3 1798.07,2933.48 cw(c1802.98,2933.48) 1802.98,2938.39 1817.71,2938.39 cw(c1817.71,2933.48) 1822.62,2933.48 1822.62,2893.3 ccw(c1827.53,2893.3) 1827.53,2888.39 1842.26,2888.39 ccw(c1842.26,2893.3) 1847.17,2893.3 1847.17,2933.48 cw(c1852.08,2933.48) 1852.08,2938.39 1866.81,2938.39 cw(c1866.81,2933.48) 1871.72,2933.48 1871.72,2893.3 ccw(c1876.63,2893.3) 1876.63,2888.39 1891.36,2888.39 ccw(c1891.36,2893.3) 1896.27,2893.3 1896.27,2933.48 cw(c1901.18,2933.48) 1901.18,2938.39 1915.91,2938.39 cw(c1915.91,2933.48) 1920.82,2933.48 1920.82,2893.3 ccw(c1925.73,2893.3) 1925.73,2888.39 1940.46,2888.39 ccw(c1940.46,2893.3) 1945.37,2893.3 1945.37,2933.48 cw(c1950.28,2933.48) 1950.28,2938.39 1965.01,2938.39 cw(c1965.01,2933.48) 1969.92,2933.48 1969.92,2893.3 ccw(c1974.83,2893.3) 1974.83,2888.39 1989.56,2888.39 ccw(c1989.56,2893.3) 1994.47,2893.3 1994.47,2933.48 cw(c1999.38,2933.48) 1999.38,2938.39 2014.11,2938.39 cw(c2014.11,2933.48) 2019.02,2933.48 2019.02,2893.3 ccw(c2023.93,2893.3) 2023.93,2888.39 2038.66,2888.39 ccw(c2038.66,2893.3) 2043.57,2893.3 2043.57,2933.48 cw(c2048.48,2933.48) 2048.48,2938.39 2063.21,2938.39 cw(c2063.21,2933.48) 2068.12,2933.48 2068.12,2894.01 ccw(c2073.03,2894.01) 2073.03,2889.1 2087.76,2889.1 ccw(c2087.76,2894.01) 2092.67,2894.01 2092.67,2918.3 cw(c2097.58,2918.3) 2097.58,2923.21 2112.31,2923.21 cw(c2112.31,2918.3) 2117.22,2918.3 ccw(c2122.13,2918.3) 2122.13,2913.39 2177.17,2913.39 2191.71,2913.39 2378.71,2726.38 MC3.67@2476.77,2726.38
SZG_PORTB_S18: J9.23 MC3.60 | length 3133.3
  L8-SIG w4.05: v1(132.05,3102.41) 149.46,3085 210,3085 283,3012 283,2941 350,2874 459,2874 856.62,2476.38 874.02,2476.38 900.09,2476.38 cw(c900.09,2471.57) 904.9,2471.57 904.9,2457.29 ccw(c909.71,2457.29) 909.71,2452.48 924.14,2452.48 ccw(c924.14,2457.29) 928.95,2457.29 928.95,2473.06 cw(c933.76,2473.06) 933.76,2477.87 948.19,2477.87 cw(c948.19,2473.06) 953,2473.06 953,2457.29 ccw(c957.81,2457.29) 957.81,2452.48 972.24,2452.48 ccw(c972.24,2457.29) 977.05,2457.29 977.05,2473.06 cw(c981.86,2473.06) 981.86,2477.87 996.29,2477.87 cw(c996.29,2473.06) 1001.1,2473.06 1001.1,2457.29 ccw(c1005.91,2457.29) 1005.91,2452.48 1020.34,2452.48 ccw(c1020.34,2457.29) 1025.15,2457.29 1025.15,2473.06 cw(c1029.96,2473.06) 1029.96,2477.87 1044.39,2477.87 cw(c1044.39,2473.06) 1049.2,2473.06 1049.2,2462.45 ccw(c1054.01,2462.45) 1054.01,2457.64 1068.44,2457.64 ccw(c1068.44,2462.45) 1073.25,2462.45 1073.25,2471.57 cw(c1078.06,2471.57) 1078.06,2476.38 1251.97,2476.38 1748.03,2476.38 1798.65,2527 2521,2527 2531,2517 2688.87,2517 v1(2755.08,2450.79)
SZG_PORTB_S19: J9.24 MC3.65 | length 3294.4
  L1-TOP w4.55: J9.24@309.65,3102.41 692.96,3102.41 744.58,3154.03 1202.39,3154.03 1525.71,2830.71 1535.43,2830.71 1537.71,2830.71 ccw(c1537.71,2835.62) 1542.62,2835.62 1542.62,2850.8 cw(c1547.53,2850.8) 1547.53,2855.71 1562.26,2855.71 cw(c1562.26,2850.8) 1567.17,2850.8 1567.17,2810.62 ccw(c1572.08,2810.62) 1572.08,2805.71 1586.81,2805.71 ccw(c1586.81,2810.62) 1591.72,2810.62 1591.72,2850.8 cw(c1596.63,2850.8) 1596.63,2855.71 1611.36,2855.71 cw(c1611.36,2850.8) 1616.27,2850.8 1616.27,2810.62 ccw(c1621.18,2810.62) 1621.18,2805.71 1635.91,2805.71 ccw(c1635.91,2810.62) 1640.82,2810.62 1640.82,2850.8 cw(c1645.73,2850.8) 1645.73,2855.71 1660.46,2855.71 cw(c1660.46,2850.8) 1665.37,2850.8 1665.37,2810.62 ccw(c1670.28,2810.62) 1670.28,2805.71 1685.01,2805.71 ccw(c1685.01,2810.62) 1689.92,2810.62 1689.92,2850.8 cw(c1694.83,2850.8) 1694.83,2855.71 1709.56,2855.71 cw(c1709.56,2850.8) 1714.47,2850.8 1714.47,2810.62 ccw(c1719.38,2810.62) 1719.38,2805.71 1734.11,2805.71 ccw(c1734.11,2810.62) 1739.02,2810.62 1739.02,2850.8 cw(c1743.93,2850.8) 1743.93,2855.71 1758.66,2855.71 cw(c1758.66,2850.8) 1763.57,2850.8 1763.57,2810.62 ccw(c1768.48,2810.62) 1768.48,2805.71 1783.21,2805.71 ccw(c1783.21,2810.62) 1788.12,2810.62 1788.12,2850.8 cw(c1793.03,2850.8) 1793.03,2855.71 1807.76,2855.71 cw(c1807.76,2850.8) 1812.67,2850.8 1812.67,2810.62 ccw(c1817.58,2810.62) 1817.58,2805.71 1832.31,2805.71 ccw(c1832.31,2810.62) 1837.22,2810.62 1837.22,2850.8 cw(c1842.13,2850.8) 1842.13,2855.71 1856.86,2855.71 cw(c1856.86,2850.8) 1861.77,2850.8 1861.77,2810.62 ccw(c1866.68,2810.62) 1866.68,2805.71 1881.41,2805.71 ccw(c1881.41,2810.62) 1886.32,2810.62 1886.32,2850.8 cw(c1891.23,2850.8) 1891.23,2855.71 1905.96,2855.71 cw(c1905.96,2850.8) 1910.87,2850.8 1910.87,2810.62 ccw(c1915.78,2810.62) 1915.78,2805.71 1930.51,2805.71 ccw(c1930.51,2810.62) 1935.42,2810.62 1935.42,2850.8 cw(c1940.33,2850.8) 1940.33,2855.71 1955.06,2855.71 cw(c1955.06,2850.8) 1959.97,2850.8 1959.97,2810.62 ccw(c1964.88,2810.62) 1964.88,2805.71 1979.61,2805.71 ccw(c1979.61,2810.62) 1984.52,2810.62 1984.52,2850.8 cw(c1989.43,2850.8) 1989.43,2855.71 2004.16,2855.71 cw(c2004.16,2850.8) 2009.07,2850.8 2009.07,2813.78 ccw(c2013.98,2813.78) 2013.98,2808.87 2028.71,2808.87 ccw(c2028.71,2813.78) 2033.62,2813.78 2033.62,2835.62 cw(c2038.53,2835.62) 2038.53,2840.53 2053.26,2840.53 cw(c2053.26,2835.62) 2058.17,2835.62 ccw(c2063.08,2835.62) 2063.08,2830.71 2106.3,2830.71 2236.22,2830.71 2360.24,2706.69 MC3.65@2476.77,2706.69
SZG_PORTB_S20: J9.25 MC3.58 | length 3133.3
  L8-SIG w4.05: v1@36.05,3070.91 164.65,3070.91 190.56,3045 212,3045 239,3018 239,2857 280,2816 370.08,2816 372.1,2816 ccw(c372.1,2820.81) 376.91,2820.81 376.91,2838.59 cw(c381.72,2838.59) 381.72,2843.4 396.15,2843.4 cw(c396.15,2838.59) 400.96,2838.59 400.96,2820.81 ccw(c405.77,2820.81) 405.77,2816 460.63,2816 477,2816 879.61,2413.39 1724.41,2413.39 1819.02,2508 2500,2508 2530,2478 2638.18,2478 v1(2685.08,2431.1)
  other v1: 39.35,3070.91
SZG_PORTB_S21: J9.26 MC3.63 | length 3294.4
  L1-TOP w4.55: J9.26@309.65,3070.91 720.51,3070.91 780.02,3130.41 1192.6,3130.41 1574.98,2748.03 1712.6,2748.03 1714.87,2748.03 ccw(c1714.87,2752.94) 1719.78,2752.94 1719.78,2768.12 cw(c1724.69,2768.12) 1724.69,2773.03 1739.42,2773.03 cw(c1739.42,2768.12) 1744.33,2768.12 1744.33,2727.94 ccw(c1749.24,2727.94) 1749.24,2723.03 1763.97,2723.03 ccw(c1763.97,2727.94) 1768.88,2727.94 1768.88,2768.12 cw(c1773.79,2768.12) 1773.79,2773.03 1788.52,2773.03 cw(c1788.52,2768.12) 1793.43,2768.12 1793.43,2727.94 ccw(c1798.34,2727.94) 1798.34,2723.03 1813.07,2723.03 ccw(c1813.07,2727.94) 1817.98,2727.94 1817.98,2768.12 cw(c1822.89,2768.12) 1822.89,2773.03 1837.62,2773.03 cw(c1837.62,2768.12) 1842.53,2768.12 1842.53,2727.94 ccw(c1847.44,2727.94) 1847.44,2723.03 1862.17,2723.03 ccw(c1862.17,2727.94) 1867.08,2727.94 1867.08,2768.12 cw(c1871.99,2768.12) 1871.99,2773.03 1886.72,2773.03 cw(c1886.72,2768.12) 1891.63,2768.12 1891.63,2727.94 ccw(c1896.54,2727.94) 1896.54,2723.03 1911.27,2723.03 ccw(c1911.27,2727.94) 1916.18,2727.94 1916.18,2768.12 cw(c1921.09,2768.12) 1921.09,2773.03 1935.82,2773.03 cw(c1935.82,2768.12) 1940.73,2768.12 1940.73,2727.94 ccw(c1945.64,2727.94) 1945.64,2723.03 1960.37,2723.03 ccw(c1960.37,2727.94) 1965.28,2727.94 1965.28,2768.12 cw(c1970.19,2768.12) 1970.19,2773.03 1984.92,2773.03 cw(c1984.92,2768.12) 1989.83,2768.12 1989.83,2727.94 ccw(c1994.74,2727.94) 1994.74,2723.03 2009.47,2723.03 ccw(c2009.47,2727.94) 2014.38,2727.94 2014.38,2768.12 cw(c2019.29,2768.12) 2019.29,2773.03 2034.02,2773.03 cw(c2034.02,2768.12) 2038.93,2768.12 2038.93,2727.94 ccw(c2043.84,2727.94) 2043.84,2723.03 2058.57,2723.03 ccw(c2058.57,2727.94) 2063.48,2727.94 2063.48,2768.12 cw(c2068.39,2768.12) 2068.39,2773.03 2083.12,2773.03 cw(c2083.12,2768.12) 2088.03,2768.12 2088.03,2727.94 ccw(c2092.94,2727.94) 2092.94,2723.03 2107.67,2723.03 ccw(c2107.67,2727.94) 2112.58,2727.94 2112.58,2768.12 cw(c2117.49,2768.12) 2117.49,2773.03 2132.22,2773.03 cw(c2132.22,2768.12) 2137.13,2768.12 2137.13,2727.94 ccw(c2142.04,2727.94) 2142.04,2723.03 2156.77,2723.03 ccw(c2156.77,2727.94) 2161.68,2727.94 2161.68,2768.12 cw(c2166.59,2768.12) 2166.59,2773.03 2181.32,2773.03 cw(c2181.32,2768.12) 2186.23,2768.12 2186.23,2731.92 ccw(c2191.14,2731.92) 2191.14,2727.01 2205.87,2727.01 ccw(c2205.87,2731.92) 2210.78,2731.92 2210.78,2752.94 cw(c2215.69,2752.94) 2215.69,2757.85 2230.42,2757.85 cw(c2230.42,2752.94) 2235.33,2752.94 ccw(c2240.24,2752.94) 2240.24,2748.03 2259.84,2748.03 2283.46,2748.03 2344.49,2687.01 MC3.63@2476.77,2687.01
SZG_PORTB_S22: J9.27 MC3.56 | length 3133.3
  L8-SIG w4.05: v1(132.05,3039.41) 158.55,3039.41 188.45,3009.51 201.49,3009.51 217,2994 217,2851 273,2795 327.84,2795 353.91,2795 cw(c353.91,2790.19) 358.72,2790.19 358.72,2769.65 ccw(c363.53,2769.65) 363.53,2764.84 377.96,2764.84 ccw(c377.96,2769.65) 382.77,2769.65 382.77,2792.08 cw(c387.58,2792.08) 387.58,2796.89 402.01,2796.89 cw(c402.01,2792.08) 406.82,2792.08 406.82,2780.28 ccw(c411.63,2780.28) 411.63,2775.47 426.06,2775.47 ccw(c426.06,2780.28) 430.87,2780.28 430.87,2790.19 cw(c435.68,2790.19) 435.68,2795 455.15,2795 457,2795 862.24,2389.76 1740.16,2389.76 1836.39,2486 2487,2486 2537,2436 2654.55,2436 2679.13,2411.42 v1(2755.08,2411.42)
